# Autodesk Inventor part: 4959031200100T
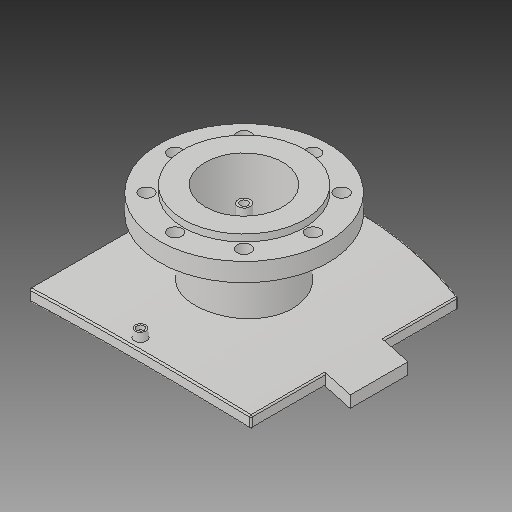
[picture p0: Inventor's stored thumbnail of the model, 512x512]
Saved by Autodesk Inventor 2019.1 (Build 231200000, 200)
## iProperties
Created: 2017-10
Part Number: 4959031200100T
Material: Generic
Description: PLASSON FLANGED BRANCH SADDLE 1200x100
Document SubType Name: Modeling
Designer: KIM
Mass: 2339.99 g
Surface Area: 3251.55 cm^2
Volume: 2339.99 cm^3
Density: 1 g/cm^3
Appearance: Default
Author: KIM
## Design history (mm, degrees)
derived "495904_495903.ipt"
feature "Solid1::495904_495903.ipt"
feature "Solid2::495904_495903.ipt"
tag "TaggingFeature1"
body "Solid1"
other parameters: "d1" = 15, "d2" = 288, "d4" = 0, "d6" = 75, "d7" = 0, "d12" = 625.6, "d13" = 14, "d14" = 135, "d16" = 5 deg, "d18" = 4, "d19" = 14, "d20" = 0, "d21" = 3, "d22" = 0, "d23" = 735, "d36" = 135, "d38" = 0, "d39" = 2, "d41" = 101, "d42" = 158, "d44" = 96, "d46" = 126.4, "d47" = 16, "d48" = 10.4, "d49" = 84, "d51" = 1224, "d53" = 0, "d54" = 18, "d57" = 0, "d59" = 360 deg, "d61" = 24, "d63" = 0, "d67" = 15, "d70" = 0, "d71" = 2, "d_1" = 158, "x_" = 15, "D_" = 16, "DN_" = 101, "t_" = 24, "s_" = 18
